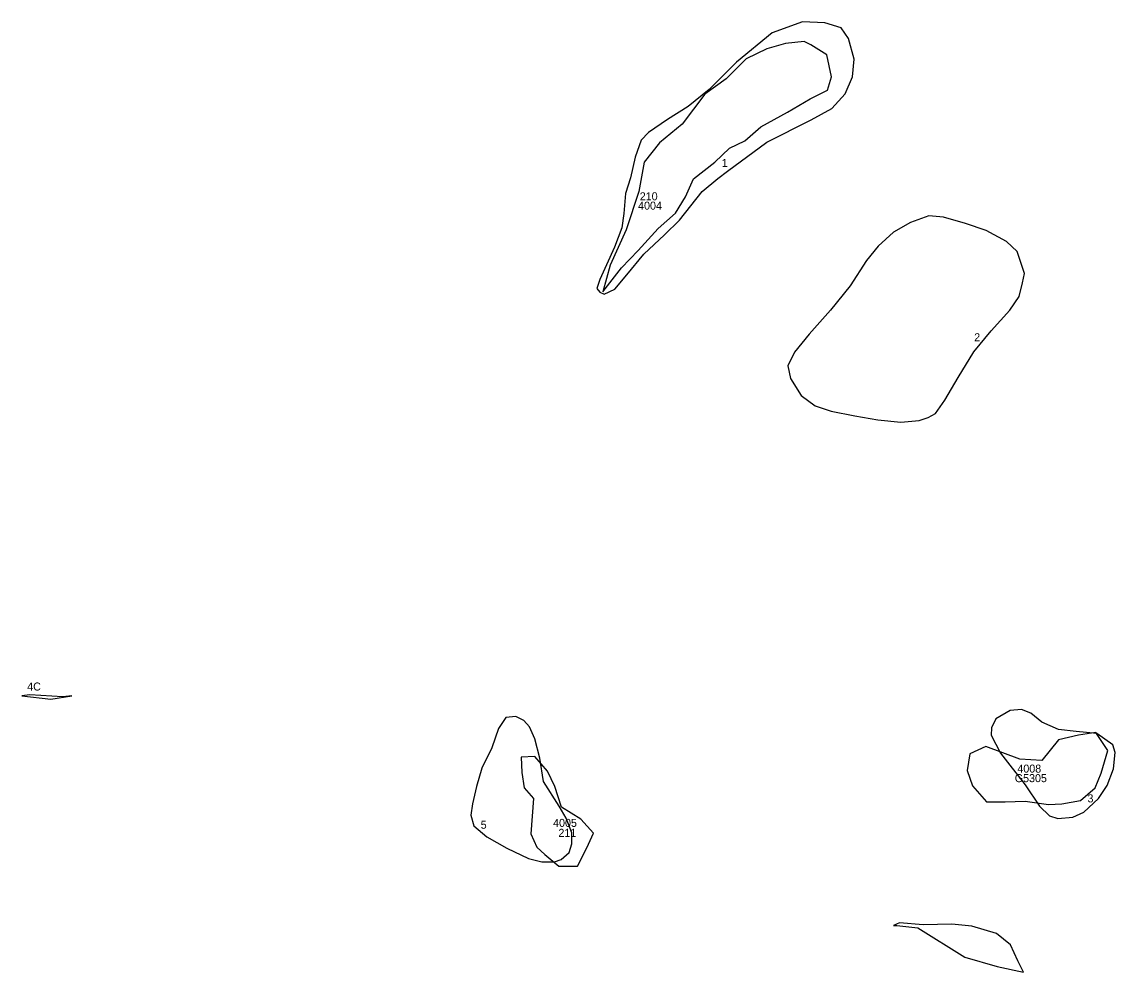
# Model space of a CAD drawing. Extents: x -439069 to -431150, y -1130245 to -1119273.
# Drawn here: x -435389 to -433750, y -1130245 to -1128822 of the extents above; entities that cross this region are included whole.
import ezdxf

# ---------------------------------------------------------------- set-up
doc = ezdxf.new("R2010")
doc.units = 0
for name, color, linetype in [('11510011_sesuvné území_Stav', 7, 'Continuous'), ('11510013_sesuvné území_Stav', 7, 'Continuous'), ('svahové nestability přírodního charakteru dočasně uklidněné', 7, 'Continuous'), ('Svahové nestability přírodního charakteru uklidněné', 7, 'Continuous')]:
    doc.layers.add(name, color=color, linetype=linetype)

msp = doc.modelspace()

# ---------------------------------------------------------------- linework, layer by layer
at = {"layer": '11510011_sesuvné území_Stav'}
for points in [[(-434206, -1128856), (-434216, -1128851), (-434244, -1128854), (-434272, -1128862), (-434303, -1128877), (-434333, -1128907), (-434365, -1128930), (-434399, -1128975), (-434433, -1129003), (-434456, -1129032), (-434464, -1129076), (-434483, -1129133), (-434507, -1129186), (-434518, -1129226), (-434490, -1129190), (-434465, -1129164), (-434435, -1129131), (-434409, -1129108), (-434394, -1129084), (-434382, -1129057), (-434350, -1129032), (-434328, -1129011), (-434305, -1129000), (-434281, -1128979), (-434241, -1128957), (-434207, -1128937), (-434181, -1128924), (-434175, -1128904), (-434182, -1128871), (-434206, -1128856)], [(-434556, -1130086), (-434542, -1130059), (-434532, -1130037), (-434551, -1130016), (-434580, -1129998), (-434590, -1129967), (-434601, -1129944), (-434620, -1129922), (-434640, -1129923), (-434639, -1129946), (-434636, -1129969), (-434622, -1129985), (-434626, -1130038), (-434617, -1130058), (-434605, -1130069), (-434584, -1130086), (-434556, -1130086)], [(-433887.3, -1130244.9), (-433896, -1130228), (-433907, -1130204), (-433928, -1130187), (-433965, -1130176), (-433995, -1130173), (-434038, -1130174), (-434073, -1130171), (-434082.3, -1130175), (-434077.2, -1130175.3), (-434045.8, -1130178.6), (-433975.1, -1130222.3), (-433926.7, -1130236.6), (-433887.3, -1130244.9)]]:
    msp.add_lwpolyline(points, dxfattribs=at)
at = {"layer": '11510013_sesuvné území_Stav'}
msp.add_lwpolyline([(-433830, -1129993), (-433802, -1129988), (-433780, -1129969), (-433771, -1129947), (-433761, -1129913), (-433779, -1129886), (-433805, -1129890), (-433835, -1129897), (-433860, -1129928), (-433893, -1129926), (-433944, -1129907), (-433968, -1129918), (-433972, -1129943), (-433964, -1129966), (-433943, -1129990), (-433915, -1129990), (-433885, -1129989), (-433850, -1129994), (-433830, -1129993)], dxfattribs=at)
at = {"layer": 'svahové nestability přírodního charakteru dočasně uklidněné'}
for points in [[(-434007.2, -1129114.4), (-434029.1, -1129112), (-434056.8, -1129122.3), (-434082.1, -1129136.8), (-434105.1, -1129157.8), (-434122.7, -1129179.2), (-434147.1, -1129217.3), (-434176.9, -1129253.6), (-434208.7, -1129289.7), (-434230.8, -1129316.3), (-434240.7, -1129336.9), (-434236.7, -1129355.8), (-434220.7, -1129381.2), (-434199.8, -1129396.7), (-434175.6, -1129404.8), (-434140.3, -1129411.7), (-434105.6, -1129417.9), (-434071.4, -1129421.3), (-434043.6, -1129418.6), (-434030.1, -1129414.2), (-434019.3, -1129408.1), (-434005.3, -1129388.5), (-433985.3, -1129354.2), (-433961.6, -1129316.1), (-433935.7, -1129284.3), (-433907.7, -1129253.4), (-433893.7, -1129233.1), (-433888.7, -1129212.8), (-433886.1, -1129198.5), (-433896.7, -1129165.9), (-433912.8, -1129150.8), (-433943.2, -1129134), (-433974.1, -1129123.9), (-434007.2, -1129114.4)], [(-434636.1, -1129868.2), (-434648.3, -1129862), (-434663.4, -1129863.8), (-434674.4, -1129880.1), (-434684.1, -1129909.1), (-434699.2, -1129939.3), (-434707.3, -1129967), (-434713.1, -1129992.7), (-434715.9, -1130009.6), (-434711.2, -1130025.7), (-434691.6, -1130042.1), (-434661.6, -1130059.4), (-434629.3, -1130074.6), (-434609.5, -1130079.9), (-434590.1, -1130079.9), (-434580.1, -1130076.3), (-434568.1, -1130066), (-434564.1, -1130052.9), (-434564.3, -1130036.5), (-434573, -1130014.1), (-434583.5, -1129996.2), (-434606.7, -1129959.3), (-434612.2, -1129924.5), (-434619.6, -1129895.6), (-434627.9, -1129877.8), (-434636.1, -1129868.2)]]:
    msp.add_lwpolyline(points, dxfattribs=at)
at = {"layer": 'Svahové nestability přírodního charakteru uklidněné'}
for points in [[(-434185.1, -1128823), (-434218.8, -1128821.8), (-434264.2, -1128838.2), (-434317.4, -1128882.3), (-434358.6, -1128923.2), (-434390.2, -1128948.4), (-434420.7, -1128968), (-434449.2, -1128987.2), (-434460.4, -1128998.7), (-434469.3, -1129024.2), (-434476.6, -1129055.4), (-434484, -1129079), (-434486.3, -1129108.5), (-434489.4, -1129130.3), (-434500.6, -1129159.1), (-434512.4, -1129185.8), (-434522.4, -1129207.8), (-434526.9, -1129221.2), (-434522.5, -1129226.4), (-434515.9, -1129229.7), (-434500.1, -1129221.9), (-434481.8, -1129200.6), (-434456.6, -1129169.5), (-434425.4, -1129140.9), (-434402.9, -1129118.5), (-434369.2, -1129075.6), (-434345.5, -1129056.1), (-434330.9, -1129045.5), (-434272.3, -1129001.8), (-434205.5, -1128968.4), (-434174.5, -1128951.5), (-434154.8, -1128929.6), (-434143.8, -1128904.3), (-434141, -1128877.6), (-434149.6, -1128846.5), (-434160.8, -1128830.5), (-434185.1, -1128823)], [(-435388.5, -1129831), (-435345.3, -1129836.3), (-435313.5, -1129831), (-435327.2, -1129832.4), (-435376.5, -1129829.8), (-435388.5, -1129831)], [(-433876.5, -1129856.9), (-433890.6, -1129851.6), (-433907.3, -1129853.1), (-433929, -1129865.8), (-433935.6, -1129879.1), (-433935.8, -1129890.1), (-433922, -1129916.8), (-433885, -1129964.5), (-433863.4, -1129996.6), (-433848.6, -1130010.9), (-433835.8, -1130014.6), (-433813.6, -1130012.9), (-433797.1, -1130005.3), (-433774.8, -1129984.9), (-433762.2, -1129965.2), (-433752.7, -1129940.4), (-433750.1, -1129915.8), (-433753.3, -1129904.5), (-433777.5, -1129887.4), (-433808.3, -1129884.3), (-433835, -1129881.5), (-433859.7, -1129870.6), (-433876.5, -1129856.9)]]:
    msp.add_lwpolyline(points, dxfattribs=at)

# ---------------------------------------------------------------- texts
at = {"layer": '11510011_sesuvné území_Stav'}
for s, p in [('210', (-434462.5, -1129089)), ('4004', (-434465, -1129103)), ('4005', (-434592.4, -1130027.4)), ('211', (-434584.4, -1130042.3))]:
    msp.add_text(s, height=12, dxfattribs=at).set_placement(p)
at = {"layer": '11510013_sesuvné území_Stav'}
for s, p in [('G5305', (-433900.5, -1129960.4)), ('4008', (-433896.6, -1129946.1))]:
    msp.add_text(s, height=12, dxfattribs=at).set_placement(p)
at = {"layer": 'svahové nestability přírodního charakteru dočasně uklidněné'}
for s, p in [('2', (-433961.3, -1129300.1)), ('5', (-434700.9, -1130030.2))]:
    msp.add_text(s, height=12, dxfattribs=at).set_placement(p)
at = {"layer": 'Svahové nestability přírodního charakteru uklidněné'}
for s, p in [('1', (-434339.6, -1129038.9)), ('4C', (-435380.5, -1129823.2)), ('3', (-433791.5, -1129990.7))]:
    msp.add_text(s, height=12, dxfattribs=at).set_placement(p)

doc.saveas('drawing.dxf')
